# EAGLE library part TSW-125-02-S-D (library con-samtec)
THROUGH-HOLE .025" SQ POST HEADER Source: Samtec TSW.pdf
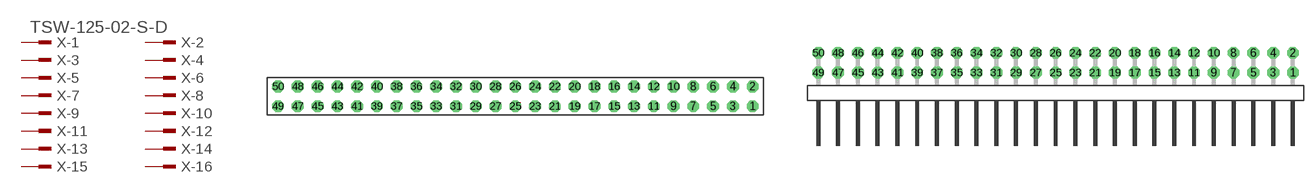
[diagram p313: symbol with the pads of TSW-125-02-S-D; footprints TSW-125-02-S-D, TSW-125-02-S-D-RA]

Designator prefix X; gates -1=MPINV -2=MPIN -3=MPIN -4=MPIN -5=MPIN -6=MPIN -7=MPIN -8=MPIN -9=MPIN -10=MPIN -11=MPIN -12=MPIN -13=MPIN -14=MPIN -15=MPIN -16=MPIN -17=MPIN -18=MPIN -19=MPIN -20=MPIN -21=MPIN -22=MPIN -23=MPIN -24=MPIN -25=MPIN -26=MPIN -27=MPIN -28=MPIN -29=MPIN -30=MPIN -31=MPIN -32=MPIN -33=MPIN -34=MPIN -35=MPIN -36=MPIN -37=MPIN -38=MPIN -39=MPIN -40=MPIN -41=MPIN -42=MPIN -43=MPIN -44=MPIN -45=MPIN -46=MPIN -47=MPIN -48=MPIN -49=MPIN -50=MPIN

## TSW-125-02-S-D (OC_FARNELL: unknown; OC_NEWARK: unknown)  [TSW-125-02-S-D]
1  -1:1  pas
2  -2:1  pas
3  -3:1  pas
4  -4:1  pas
5  -5:1  pas
6  -6:1  pas
7  -7:1  pas
8  -8:1  pas
9  -9:1  pas
10  -10:1  pas
11  -11:1  pas
12  -12:1  pas
13  -13:1  pas
14  -14:1  pas
15  -15:1  pas
16  -16:1  pas
17  -17:1  pas
18  -18:1  pas
19  -19:1  pas
20  -20:1  pas
21  -21:1  pas
22  -22:1  pas
23  -23:1  pas
24  -24:1  pas
25  -25:1  pas
26  -26:1  pas
27  -27:1  pas
28  -28:1  pas
29  -29:1  pas
30  -30:1  pas
31  -31:1  pas
32  -32:1  pas
33  -33:1  pas
34  -34:1  pas
35  -35:1  pas
36  -36:1  pas
37  -37:1  pas
38  -38:1  pas
39  -39:1  pas
40  -40:1  pas
41  -41:1  pas
42  -42:1  pas
43  -43:1  pas
44  -44:1  pas
45  -45:1  pas
46  -46:1  pas
47  -47:1  pas
48  -48:1  pas
49  -49:1  pas
50  -50:1  pas

## TSW-125-02-S-D-RA (OC_FARNELL: unknown; OC_NEWARK: unknown)  [TSW-125-02-S-D-RA]
Pads as for TSW-125-02-S-D

## Footprint TSW-125-02-S-D (pad centres in mm)
THROUGH-HOLE .025" SQ POST HEADER Source: Samtec TSW.pdf
drill 1 pad 1.5 octagon: 1 30.48,-1.27; 2 30.48,1.27; 3 27.94,-1.27; 4 27.94,1.27; 5 25.4,-1.27; 6 25.4,1.27; 7 22.86,-1.27; 8 22.86,1.27; 9 20.32,-1.27; 10 20.32,1.27; 11 17.78,-1.27; 12 17.78,1.27; 13 15.24,-1.27; 14 15.24,1.27; 15 12.7,-1.27; 16 12.7,1.27; 17 10.16,-1.27; 18 10.16,1.27; 19 7.62,-1.27; 20 7.62,1.27; 21 5.08,-1.27; 22 5.08,1.27; 23 2.54,-1.27; 24 2.54,1.27; 25 0,-1.27; 26 0,1.27; 27 -2.54,-1.27; 28 -2.54,1.27; 29 -5.08,-1.27; 30 -5.08,1.27; 31 -7.62,-1.27; 32 -7.62,1.27; 33 -10.16,-1.27; 34 -10.16,1.27; 35 -12.7,-1.27; 36 -12.7,1.27; 37 -15.24,-1.27; 38 -15.24,1.27; 39 -17.78,-1.27; 40 -17.78,1.27; 41 -20.32,-1.27; 42 -20.32,1.27; 43 -22.86,-1.27; 44 -22.86,1.27; 45 -25.4,-1.27; 46 -25.4,1.27; 47 -27.94,-1.27; 48 -27.94,1.27; 49 -30.48,-1.27; 50 -30.48,1.27

## Footprint TSW-125-02-S-D-RA (pad centres in mm)
THROUGH-HOLE .025" SQ POST HEADER Source: Samtec TSW.pdf
drill 1 pad 1.5 octagon: 1 30.48,1.524; 2 30.48,4.064; 3 27.94,1.524; 4 27.94,4.064; 5 25.4,1.524; 6 25.4,4.064; 7 22.86,1.524; 8 22.86,4.064; 9 20.32,1.524; 10 20.32,4.064; 11 17.78,1.524; 12 17.78,4.064; 13 15.24,1.524; 14 15.24,4.064; 15 12.7,1.524; 16 12.7,4.064; 17 10.16,1.524; 18 10.16,4.064; 19 7.62,1.524; 20 7.62,4.064; 21 5.08,1.524; 22 5.08,4.064; 23 2.54,1.524; 24 2.54,4.064; 25 0,1.524; 26 0,4.064; 27 -2.54,1.524; 28 -2.54,4.064; 29 -5.08,1.524; 30 -5.08,4.064; 31 -7.62,1.524; 32 -7.62,4.064; 33 -10.16,1.524; 34 -10.16,4.064; 35 -12.7,1.524; 36 -12.7,4.064; 37 -15.24,1.524; 38 -15.24,4.064; 39 -17.78,1.524; 40 -17.78,4.064; 41 -20.32,1.524; 42 -20.32,4.064; 43 -22.86,1.524; 44 -22.86,4.064; 45 -25.4,1.524; 46 -25.4,4.064; 47 -27.94,1.524; 48 -27.94,4.064; 49 -30.48,1.524; 50 -30.48,4.064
